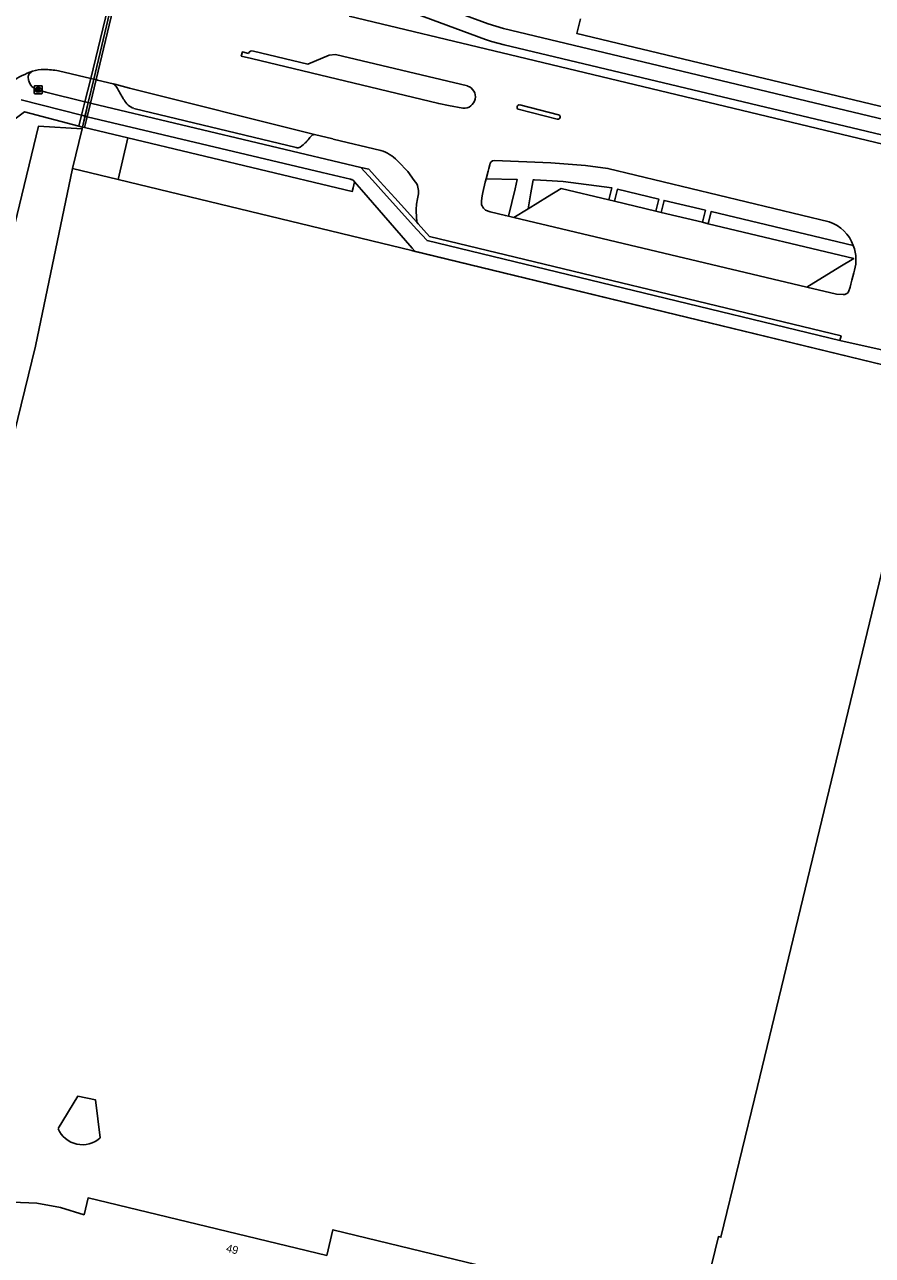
# Model space of a CAD drawing. Extents: x 163046 to 165074, y 382019 to 382874.
# Drawn here: x 163144 to 163250, y 382537 to 382690.8 of the extents above; entities that cross this region are included whole.
import ezdxf

# ---------------------------------------------------------------- set-up
doc = ezdxf.new("R2010")
doc.units = 0
for name, color, linetype in [('IMGEO_Berm_groen', 7, 'Continuous'), ('IMGEO_Fietspad_gesloten', 7, 'Continuous'), ('IMGEO_Fietspad_open', 7, 'Continuous'), ('IMGEO_Groenvoorziening', 7, 'Continuous'), ('IMGEO_Hek', 7, 'Continuous'), ('IMGEO_Kolk', 7, 'Continuous'), ('IMGEO_Muur', 7, 'Continuous'), ('IMGEO_Pand', 7, 'Continuous'), ('IMGEO_Pand_nummerreeks', 7, 'Continuous'), ('IMGEO_Parkeervlak_open', 7, 'Continuous'), ('IMGEO_Rijbaan_lokaal_gesloten', 7, 'Continuous'), ('IMGEO_Verkeerseiland_gesloten', 7, 'Continuous'), ('IMGEO_Verkeerseiland_open', 7, 'Continuous'), ('IMGEO_Voetpad_gesloten', 7, 'Continuous'), ('IMGEO_Voetpad_open', 7, 'Continuous')]:
    doc.layers.add(name, color=color, linetype=linetype)

msp = doc.modelspace()

# ---------------------------------------------------------------- linework, layer by layer
at = {"layer": 'IMGEO_Berm_groen'}
for points in [[(163151.2, 382677.8), (163145.77, 382678.15), (163123.53, 382586.2), (163123.07, 382584.31), (163123.07, 382584.29), (163125.01, 382583.22)], [(163151.26, 382678.03), (163151.2, 382677.8)]]:
    msp.add_lwpolyline(points, dxfattribs=at)
at = {"layer": 'IMGEO_Fietspad_gesloten'}
for points in [[(163151.55, 382681.19), (163151.14, 382679.49)], [(163151.55, 382681.19), (163151.98, 382681.08)], [(163151.98, 382681.08), (163151.58, 382679.38)], [(163151.84, 382679.31), (163152.25, 382681.02)], [(163152.25, 382681.02), (163151.98, 382681.08)], [(163151.14, 382679.49), (163151.58, 382679.38)], [(163151.84, 382679.31), (163151.58, 382679.38)]]:
    msp.add_lwpolyline(points, dxfattribs=at)
at = {"layer": 'IMGEO_Fietspad_open'}
for points in [[(163172.35, 382701.93), (163176, 382700.52), (163201.96, 382690.91), (163203.88, 382690.32), (163252.46, 382678.73)], [(163252.01, 382676.83), (163203.95, 382688.31), (163202.36, 382688.7), (163201.62, 382688.96), (163172.54, 382699.75), (163171.68, 382699.94), (163168.8, 382700.21)], [(163144.53, 382683.91), (163144.46, 382684.27)], [(163151.55, 382681.19), (163146.68, 382682.38), (163145.73, 382682.68)], [(163143.58, 382681.41), (163151.14, 382679.49)], [(163152.25, 382681.02), (163152.42, 382680.98), (163186.03, 382672.99)], [(163184.96, 382671.45), (163184.91, 382671.47), (163184.85, 382671.48), (163184.74, 382671.51), (163181.21, 382672.34), (163151.84, 382679.31)], [(163186.03, 382672.99), (163187.49, 382671.37), (163189.25, 382669.42), (163193.05, 382665.23), (163194.32, 382663.83), (163245.93, 382651.34)], [(163185.25, 382671.17), (163185.18, 382671.29)], [(163192.83, 382662.48), (163192.48, 382662.89), (163186.12, 382670.17), (163185.25, 382671.17)], [(163256.82, 382646.99), (163251.27, 382648.33), (163192.83, 382662.48)]]:
    msp.add_lwpolyline(points, dxfattribs=at)
for centre, radius, start, end in [((163145.4, 382684.19), 0.944, 149.9145, 175.3115), ((163145.73, 382683.69), 1.5, 118.4672, 139.538), ((163145.98, 382684.13), 1.47, 188.9749, 260.2693), ((163184.83, 382671.05), 0.42, 34.8324, 71.6864)]:
    msp.add_arc(centre, radius, start, end, dxfattribs=at)
at = {"layer": 'IMGEO_Groenvoorziening'}
for points in [[(163151.2, 382677.8), (163149.99, 382672.86)], [(163156.94, 382676.68), (163155.71, 382671.47)], [(163149.99, 382672.86), (163145.37, 382650.66), (163131.6, 382594.38), (163136.62, 382593.15), (163133.38, 382579.94)], [(163155.71, 382671.47), (163149.99, 382672.86)], [(163192.83, 382662.48), (163192.41, 382662.59), (163155.71, 382671.47)]]:
    msp.add_lwpolyline(points, dxfattribs=at)
at = {"layer": 'IMGEO_Hek'}
for points in [[(163156.8, 382701.4), (163152.68, 382684.01)], [(163152.68, 382684.01), (163151.98, 382681.08)], [(163151.98, 382681.08), (163151.61, 382679.51)], [(163151.61, 382679.51), (163151.26, 382678.03)], [(163151.2, 382677.8), (163145.77, 382678.15), (163123.53, 382586.2)], [(163155.71, 382671.47), (163149.99, 382672.86), (163151.2, 382677.8)], [(163151.26, 382678.03), (163151.2, 382677.8)], [(163192.41, 382662.59), (163155.71, 382671.47)], [(163251.27, 382648.33), (163192.41, 382662.59)]]:
    msp.add_lwpolyline(points, dxfattribs=at)
at = {"layer": 'IMGEO_Kolk'}
for p, q in [((163145.23, 382682.26), (163145.23, 382683.11)), ((163145.31, 382683.19), (163146.16, 382683.19)), ((163145.72, 382682.96), (163145.74, 382682.96)), ((163145.74, 382682.41), (163145.72, 382682.41)), ((163146.23, 382683.11), (163146.23, 382682.26)), ((163146.16, 382682.18), (163145.31, 382682.18))]:
    msp.add_line(p, q, dxfattribs=at)
for points in [[(163145.23, 382682.26), (163145.23, 382683.11)], [(163145.31, 382683.19), (163146.16, 382683.19)], [(163145.55, 382682.88), (163145.68, 382682.88), (163145.68, 382682.73), (163145.8, 382682.88), (163145.97, 382682.88), (163145.82, 382682.73), (163145.98, 382682.48), (163145.82, 382682.48), (163145.74, 382682.65), (163145.68, 382682.58), (163145.68, 382682.48), (163145.55, 382682.48), (163145.55, 382682.88)], [(163146.23, 382683.11), (163146.23, 382682.26)], [(163146.16, 382682.18), (163145.31, 382682.18)]]:
    msp.add_lwpolyline(points, dxfattribs=at)
for centre, start, end in [((163145.31, 382683.11), 91.552, 178.448), ((163145.31, 382683.11), 91.552, 178.448), ((163146.16, 382683.11), 1.552, 88.448), ((163146.16, 382683.11), 1.552, 88.448), ((163145.31, 382682.26), 181.552, 268.448), ((163145.31, 382682.26), 181.552, 268.448), ((163146.16, 382682.26), 271.552, 358.448), ((163146.16, 382682.26), 271.552, 358.448)]:
    msp.add_arc(centre, 0.0765, start, end, dxfattribs=at)
for centre, major_axis, ratio, start_param, end_param in [((163145.72, 382682.68), (-0.387, 0.002), 0.722429, 4.712389, 7.853982), ((163145.74, 382682.68), (-0.39, 0.002), 0.717154, 1.570796, 4.712389)]:
    msp.add_ellipse(centre, major_axis=major_axis, ratio=ratio, start_param=start_param, end_param=end_param, dxfattribs=at)
at = {"layer": 'IMGEO_Muur'}
msp.add_lwpolyline([(163148.21, 382552.88), (163150.66, 382556.93), (163152.9, 382556.47), (163153.47, 382551.73)], dxfattribs=at)
msp.add_arc((163151.25, 382554.19), 3.32, 203.4072, 311.9901, dxfattribs=at)
at = {"layer": 'IMGEO_Pand'}
for points in [[(163228.25, 382529.15), (163230.73, 382539.39), (163231.05, 382539.31), (163235.6, 382558.13), (163257.08, 382646.93)], [(163148.21, 382552.88), (163150.66, 382556.93), (163152.9, 382556.47), (163153.47, 382551.73)], [(163126.28, 382536.5), (163128.53, 382538.55), (163130.99, 382540.32), (163133.68, 382541.72), (163136.53, 382542.76), (163139.51, 382543.41), (163142.52, 382543.68), (163145.56, 382543.56), (163148.52, 382543.03), (163151.46, 382542.12), (163151.96, 382544.22), (163159.39, 382542.42), (163181.78, 382537.03), (163182.56, 382540.25), (163228.25, 382529.15)]]:
    msp.add_lwpolyline(points, dxfattribs=at)
msp.add_arc((163151.25, 382554.19), 3.32, 203.4072, 311.9901, dxfattribs=at)
at = {"layer": 'IMGEO_Parkeervlak_open'}
for points in [[(163217.04, 382668.92), (163211.08, 382670.35), (163209.36, 382669.29), (163206.95, 382667.81)], [(163222.91, 382667.52), (163217.76, 382668.75)], [(163223.59, 382667.35), (163228.74, 382666.12)], [(163241.78, 382658.01), (163245.93, 382660.55), (163247.64, 382661.6), (163229.45, 382665.95)]]:
    msp.add_lwpolyline(points, dxfattribs=at)
at = {"layer": 'IMGEO_Rijbaan_lokaal_gesloten'}
for points in [[(163152.28, 382684.11), (163156.57, 382701.71)], [(163156.86, 382701.64), (163156.8, 382701.4), (163152.68, 382684.01)], [(163152.95, 382683.95), (163157.18, 382701.57)], [(163184.58, 382691.88), (163203.7, 382687.3), (163251.29, 382675.9)], [(163172, 382687.21), (163171.24, 382687.42), (163171.1, 382686.9), (163172.4, 382686.57), (163195.78, 382680.95), (163197.02, 382680.7), (163198.8, 382680.38)], [(163182.86, 382687.1), (163182.09, 382687.01), (163179.43, 382685.88), (163172.62, 382687.52)], [(163199.37, 382683.16), (163182.86, 382687.1)], [(163148.26, 382685.04), (163152.28, 382684.11)], [(163152.68, 382684.01), (163152.28, 382684.11)], [(163152.95, 382683.95), (163152.68, 382684.01)], [(163155.08, 382683.44), (163153.14, 382683.9), (163152.95, 382683.95)], [(163180.26, 382677.08), (163180.09, 382677.12), (163157.14, 382682.88), (163155.3, 382683.39), (163155.08, 382683.44)], [(163156.45, 382681.43), (163156.35, 382681.57), (163156.25, 382681.75), (163156.14, 382681.93), (163156.04, 382682.11), (163155.94, 382682.29), (163155.84, 382682.47), (163155.77, 382682.59), (163155.63, 382682.84), (163155.48, 382683.08)], [(163177.98, 382675.46), (163157.67, 382680.36)], [(163205.72, 382680.24), (163210.6, 382679.01)], [(163210.76, 382679.56), (163205.9, 382680.8)], [(163179.93, 382676.98), (163179.67, 382676.7), (163179.6, 382676.6), (163179.45, 382676.43), (163179.3, 382676.27), (163179.15, 382676.11), (163179.08, 382676.05), (163178.99, 382675.97), (163178.83, 382675.82), (163178.66, 382675.68), (163178.46, 382675.52)], [(163188.55, 382675.11), (163182.57, 382676.53), (163182.54, 382676.54), (163180.26, 382677.08)], [(163193.03, 382670.93), (163192.72, 382671.36), (163191.92, 382672.45), (163190.72, 382673.72), (163190.58, 382673.84)], [(163202.16, 382673.29), (163202.04, 382672.84), (163201.96, 382672.53), (163201.69, 382671.54)], [(163244.58, 382666.19), (163216.93, 382672.85), (163214.11, 382673.21), (163209.8, 382673.56), (163202.74, 382673.86)], [(163201.69, 382671.54), (163201.61, 382671.25), (163201.58, 382671.12), (163201.28, 382669.86), (163201.2, 382669.43), (163201.13, 382668.82)], [(163193.03, 382666.15), (163192.94, 382667.5)], [(163201.62, 382667.65), (163202.22, 382667.42), (163204.11, 382666.96), (163204.51, 382666.87)], [(163245.93, 382651.34), (163246.07, 382651.92), (163194.64, 382664.36), (163193.22, 382665.93), (163193.03, 382666.15)], [(163204.51, 382666.87), (163205.16, 382666.72)], [(163205.16, 382666.72), (163241.78, 382658.01)], [(163246.98, 382657.43), (163247.2, 382658.02), (163247.29, 382658.4), (163247.42, 382658.88), (163247.67, 382659.82), (163247.74, 382660.16), (163247.89, 382660.88), (163247.93, 382661.53)], [(163241.78, 382658.01), (163245.48, 382657.16), (163246.32, 382657.09)], [(163251.69, 382650.06), (163245.93, 382651.34)]]:
    msp.add_lwpolyline(points, dxfattribs=at)
for centre, radius, start, end in [((163172.47, 382687.05), 0.49, 71.986, 161.9583), ((163149.46, 382672.86), 12.94, 110.0878, 135.1768), ((163146.37, 382680.63), 4.58, 88.7546, 107.2078), ((163146.6, 382677.03), 8.18, 78.3294, 90.9471), ((163154.56, 382682.48), 1.09, 33.2505, 61.8458), ((163198.94, 382681.8), 1.42, 264.5645, 72.3711), ((163158.36, 382682.39), 2.14, 206.6047, 251.1963), ((163205.86, 382680.5), 0.297, 83.2931, 240.7079), ((163210.69, 382679.29), 0.286, 252.4416, 75.6401), ((163180.2, 382676.69), 0.398, 80.6733, 132.6622), ((163178.14, 382676.07), 0.636, 254.95, 300.1152), ((163187.11, 382670.55), 4.78, 43.4319, 72.4406), ((163202.77, 382673.25), 0.614, 92.8599, 176.1471), ((163190.87, 382669.94), 2.38, 343.5917, 24.5942), ((163203.21, 382667.18), 10.27, 168.2845, 178.2168), ((163202.25, 382668.6), 1.14, 168.553, 236.7488), ((163242.98, 382661.59), 4.88, 19.4653, 70.8224), ((163244.32, 382661.65), 3.6, 358.1332, 25.6407), ((163246.28, 382657.98), 0.895, 273.0055, 321.5178)]:
    msp.add_arc(centre, radius, start, end, dxfattribs=at)
at = {"layer": 'IMGEO_Verkeerseiland_gesloten'}
for points in [[(163152.28, 382684.11), (163151.55, 382681.19)], [(163151.98, 382681.08), (163152.68, 382684.01)], [(163152.95, 382683.95), (163152.25, 382681.02)]]:
    msp.add_lwpolyline(points, dxfattribs=at)
at = {"layer": 'IMGEO_Verkeerseiland_open'}
msp.add_lwpolyline([(163193.03, 382666.15), (163190.28, 382669.18), (163188.48, 382671.17), (163187.06, 382672.75), (163186.03, 382672.99)], dxfattribs=at)
at = {"layer": 'IMGEO_Voetpad_gesloten'}
for points in [[(163151.58, 382679.38), (163151.26, 382678.03)], [(163151.52, 382677.97), (163151.84, 382679.31)], [(163151.26, 382678.03), (163151.52, 382677.97)]]:
    msp.add_lwpolyline(points, dxfattribs=at)
at = {"layer": 'IMGEO_Voetpad_open'}
for points in [[(163252.81, 382680.18), (163213.05, 382689.7), (163213.5, 382691.55)], [(163150.8, 382678.15), (163144.02, 382679.91), (163140.43, 382677.25), (163135.61, 382663.66), (163134.27, 382660.75), (163135.52, 382660.15), (163131.75, 382652.64), (163129.46, 382647.96), (163128.29, 382645.56), (163124.16, 382637.14), (163120.33, 382632.45), (163111.07, 382613.55), (163105.14, 382601.72), (163104.49, 382600.41)], [(163151.14, 382679.49), (163150.8, 382678.15)], [(163150.8, 382678.15), (163151.26, 382678.03)], [(163151.52, 382677.97), (163156.94, 382676.68)], [(163156.94, 382676.68), (163183.04, 382670.45), (163184.97, 382669.98), (163185.07, 382670.42), (163185.25, 382671.17)], [(163201.69, 382671.54), (163205.6, 382671.45), (163205.32, 382670.29), (163204.51, 382666.87)], [(163206.95, 382667.81), (163207.3, 382669.79), (163207.54, 382671.19), (163207.58, 382671.42), (163207.73, 382671.42), (163209.26, 382671.35), (163211.32, 382671.22), (163217.4, 382670.43), (163217.04, 382668.92)], [(163217.76, 382668.75), (163218.12, 382670.26), (163223.27, 382669.03), (163222.91, 382667.52)], [(163217.04, 382668.92), (163217.76, 382668.75)], [(163223.59, 382667.35), (163223.95, 382668.86), (163229.1, 382667.63), (163228.74, 382666.12)], [(163205.16, 382666.72), (163206.95, 382667.81)], [(163222.91, 382667.52), (163223.59, 382667.35)], [(163229.45, 382665.95), (163229.81, 382667.46), (163247.57, 382663.21)], [(163228.74, 382666.12), (163229.45, 382665.95)]]:
    msp.add_lwpolyline(points, dxfattribs=at)

# ---------------------------------------------------------------- texts
at = {"layer": 'IMGEO_Pand_nummerreeks'}
msp.add_text('49', height=1, rotation=346.4495, dxfattribs=at).set_placement((163169.14, 382537.5))

doc.saveas('drawing.dxf')
